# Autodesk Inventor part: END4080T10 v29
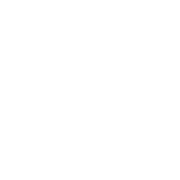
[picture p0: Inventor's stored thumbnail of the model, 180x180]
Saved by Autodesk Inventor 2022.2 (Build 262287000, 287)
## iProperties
Created: 2024-09
Part Number: END4080T10 v29
Material: Generico
Document SubType Name: Modeling
Designer: 18907419
Density: 1 g/cm^3
Appearance: Default
Author: 18907419
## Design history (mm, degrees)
